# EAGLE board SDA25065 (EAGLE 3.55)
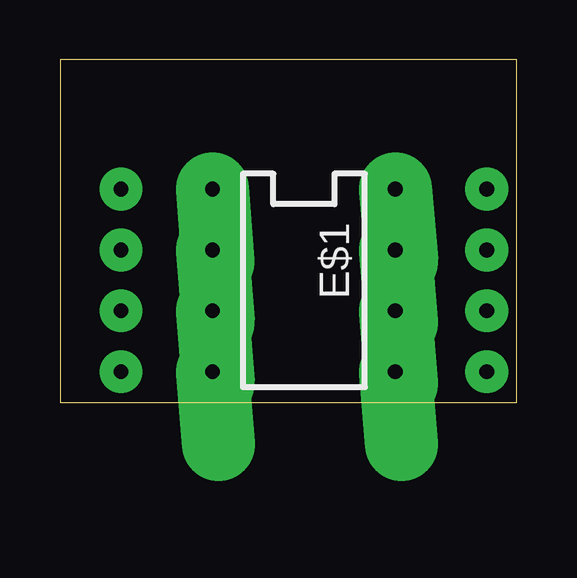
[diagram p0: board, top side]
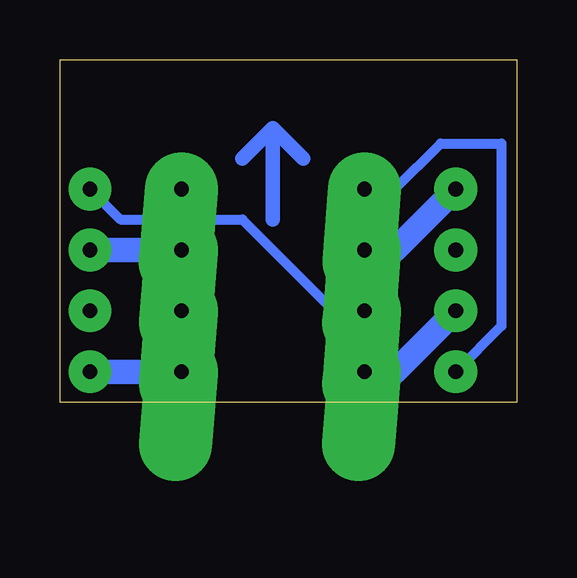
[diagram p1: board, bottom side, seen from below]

Size 19.03 x 14.28 mm. Coordinates in mm from the lower left corner, seen from the top.
Outline: 0,0 19.03,0 19.03,14.28 0,14.28 0,0
Copper layers used: Bottom

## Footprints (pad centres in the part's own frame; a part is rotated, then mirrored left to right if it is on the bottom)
L-8B = drill 0.61 pad 3.048 offset:  0,0;  2.54,0;  5.08,0;  7.62,0;  7.62,7.62;  5.08,7.62;  2.54,7.62;  0,7.62
D70 = drill 0.61 pad 1.778 round:  0,0

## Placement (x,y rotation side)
E$1  [L-8B]  6.35,8.89 270 top
N1  Pin13  [D70]  2.54,8.89 0 top
N2  Pin14  [D70]  2.54,6.35 0 top
N3  Pin15  [D70]  2.54,3.81 0 top
N4  Pin16  [D70]  2.54,1.27 0 top
N5  Pin20  [D70]  17.78,8.89 0 top
N6  Pin19  [D70]  17.78,6.35 0 top
N7  Pin18  [D70]  17.78,3.81 0 top
N8  Pin17  [D70]  17.78,1.27 0 top

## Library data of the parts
E$1 N1-N8 = holg_plt

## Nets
S$1: E$1. N1.
S$2: E$1. N3.
S$3: E$1. N4.
S$4: E$1. N5.
S$5: E$1. N6.
S$6: E$1. N8.

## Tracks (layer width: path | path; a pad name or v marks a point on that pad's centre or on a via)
S$1
  Bottom 1.016: 6.35,6.35 5.08,6.35 N1.
S$2
  Bottom 1.016: 6.35,1.27 5.08,1.27 N3.
S$3
  Bottom 0.406: 6.35,8.89 5.08,8.89 3.17,10.79 0.64,10.79 0.64,3.17 N4.
S$4
  Bottom 0.406: N5. 16.51,7.62 11.43,7.62 7.62,3.81 6.35,3.81
S$5
  Bottom 1.016: 13.97,6.35 N6.
S$6
  Bottom 1.016: 13.97,1.27 N8.
S$9
  Bottom 0.61: 10.16,7.62 10.16,11.43 | 10.16,11.43 8.89,10.16 | 10.16,11.43 11.43,10.16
